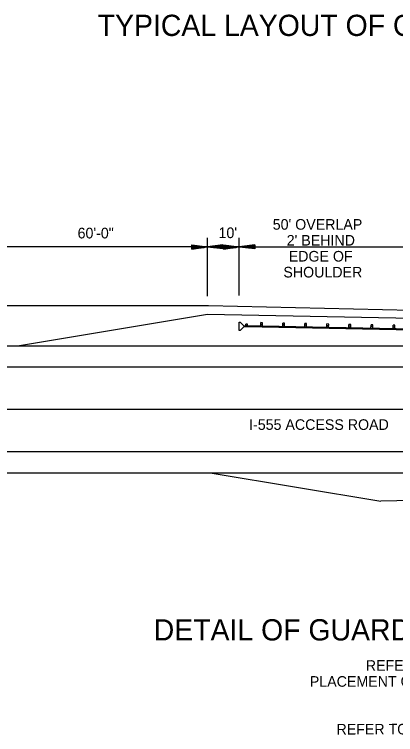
# Model space of a CAD drawing. Extents: x -2842 to 2681, y -2139 to 474.
# Drawn here: x -2490.2 to -2274.9, y -1820.5 to -1413.5 of the extents above; entities that cross this region are included whole.
import ezdxf

# ---------------------------------------------------------------- set-up
doc = ezdxf.new("R2010")
doc.units = 0
for name, color, linetype in [('Default', 7, 'Continuous'), ('R_Border', 7, 'Continuous'), ('R_Border Notes', 7, 'Continuous'), ('R_Grid', 7, 'Continuous')]:
    doc.layers.add(name, color=color, linetype=linetype)

msp = doc.modelspace()

# ---------------------------------------------------------------- linework, layer by layer
at = {"layer": 'Default'}
for p, q in [((-2381.26, -1583.13), (-2488.43, -1600.97)), ((-2263.31, -1585.48), (-2381.26, -1583.13)), ((-2263.45, -1592), (-2359.64, -1590.08)), ((-2359.58, -1589.54), (-2359.56, -1588.54)), ((-2263.43, -1591.46), (-2359.58, -1589.54)), ((-2359.08, -1589.54), (-2359.58, -1589.54)), ((-2358.57, -1588.56), (-2359.56, -1588.54)), ((-2358.59, -1589.56), (-2358.57, -1588.56)), ((-2351.11, -1589.71), (-2351.07, -1587.72)), ((-2350.61, -1589.73), (-2351.11, -1589.71)), ((-2350.09, -1588.73), (-2351.09, -1588.71)), ((-2350.07, -1587.74), (-2351.07, -1587.72)), ((-2350.11, -1589.73), (-2350.61, -1589.73)), ((-2350.11, -1589.73), (-2350.07, -1587.74)), ((-2338.65, -1589.97), (-2338.61, -1587.97)), ((-2338.15, -1589.97), (-2338.65, -1589.97)), ((-2337.63, -1588.99), (-2338.63, -1588.97)), ((-2337.61, -1587.99), (-2338.61, -1587.97)), ((-2337.65, -1589.99), (-2338.15, -1589.97)), ((-2337.65, -1589.99), (-2337.61, -1587.99)), ((-2326.19, -1590.21), (-2326.15, -1588.21)), ((-2325.2, -1589.23), (-2326.19, -1589.21)), ((-2325.71, -1590.23), (-2326.19, -1590.21)), ((-2325.16, -1588.23), (-2326.15, -1588.21)), ((-2325.2, -1590.23), (-2325.71, -1590.23)), ((-2325.2, -1590.23), (-2325.16, -1588.23)), ((-2313.76, -1590.45), (-2313.72, -1588.45)), ((-2313.26, -1590.47), (-2313.76, -1590.45)), ((-2312.74, -1589.49), (-2313.74, -1589.45)), ((-2312.72, -1588.49), (-2313.72, -1588.45)), ((-2312.76, -1590.49), (-2313.26, -1590.47)), ((-2312.76, -1590.49), (-2312.72, -1588.49)), ((-2301.3, -1590.7), (-2301.26, -1588.71)), ((-2300.8, -1590.72), (-2301.3, -1590.7)), ((-2300.28, -1589.73), (-2301.28, -1589.71)), ((-2300.26, -1588.73), (-2301.26, -1588.71)), ((-2300.3, -1590.72), (-2300.8, -1590.72)), ((-2300.3, -1590.72), (-2300.26, -1588.73)), ((-2288.84, -1590.94), (-2288.8, -1588.95)), ((-2288.34, -1590.96), (-2288.84, -1590.94)), ((-2287.83, -1589.97), (-2288.82, -1589.95)), ((-2287.81, -1588.97), (-2288.8, -1588.95)), ((-2287.85, -1590.96), (-2288.34, -1590.96)), ((-2287.85, -1590.96), (-2287.81, -1588.97)), ((-2276.39, -1591.2), (-2276.35, -1589.21)), ((-2275.89, -1591.2), (-2276.39, -1591.2)), ((-2275.37, -1590.23), (-2276.37, -1590.21)), ((-2275.35, -1589.23), (-2276.35, -1589.21)), ((-2275.39, -1591.22), (-2275.89, -1591.2)), ((-2275.39, -1591.22), (-2275.35, -1589.23)), ((-2381.26, -1600.97), (-2773.74, -1600.97)), ((-1815.02, -1600.97), (-2381.26, -1600.97)), ((-1662.85, -1612.93), (-2773.74, -1612.93)), ((-1661.2, -1660.76), (-2773.74, -1660.76)), ((-1815.02, -1672.72), (-2773.74, -1672.72)), ((-2378.47, -1672.72), (-2283.36, -1688.59)), ((-2163.68, -1686.21), (-2283.36, -1688.59))]:
    msp.add_line(p, q, dxfattribs=at)
msp.add_lwpolyline([(-2500.66, -1577.94), (-2380.62, -1578.11), (-2266.04, -1580.67)], dxfattribs=at)
msp.add_lwpolyline([(-2360.71, -1589.52), (-2359.22, -1589.54), (-2359.24, -1590.08), (-2360.73, -1590.06), (-2362.69, -1592.09), (-2363.34, -1592.07), (-2363.32, -1587.47), (-2362.67, -1587.49)], close=True, dxfattribs=at)
at = {"layer": 'R_Border Notes'}
for p, q in [((-2381.26, -1572.68), (-2381.26, -1539.7)), ((-2363.24, -1572.28), (-2363.24, -1539.7)), ((-2363.24, -1544.95), (-2500.85, -1544.95)), ((-2390.09, -1543.81), (-2381.26, -1544.95)), ((-2390.08, -1546.1), (-2390.09, -1543.81)), ((-2390.09, -1544.03), (-2388.36, -1544.03)), ((-2390.09, -1544.27), (-2386.57, -1544.26)), ((-2390.09, -1544.49), (-2384.78, -1544.5)), ((-2390.09, -1544.73), (-2383.05, -1544.73)), ((-2381.26, -1544.95), (-2390.09, -1544.95)), ((-2390.09, -1545.41), (-2384.78, -1545.4)), ((-2390.09, -1545.87), (-2388.35, -1545.86)), ((-2390.08, -1546.1), (-2381.26, -1544.95)), ((-2390.08, -1545.18), (-2383.05, -1545.18)), ((-2390.08, -1545.64), (-2386.56, -1545.64)), ((-2372.44, -1543.8), (-2381.26, -1544.95)), ((-2381.26, -1544.95), (-2372.44, -1544.95)), ((-2372.44, -1546.09), (-2381.26, -1544.95)), ((-2372.44, -1544.72), (-2379.47, -1544.72)), ((-2372.44, -1545.17), (-2379.47, -1545.18)), ((-2372.44, -1544.49), (-2377.74, -1544.5)), ((-2372.43, -1545.41), (-2377.74, -1545.41)), ((-2372.44, -1544.26), (-2375.96, -1544.26)), ((-2372.43, -1545.63), (-2375.96, -1545.64)), ((-2372.44, -1544.03), (-2374.17, -1544.04)), ((-2372.44, -1545.87), (-2374.17, -1545.87)), ((-2372.44, -1543.8), (-2372.44, -1546.09)), ((-2372.07, -1543.81), (-2363.24, -1544.95)), ((-2372.07, -1546.1), (-2372.07, -1543.81)), ((-2372.07, -1544.03), (-2370.34, -1544.03)), ((-2372.07, -1544.27), (-2368.55, -1544.26)), ((-2372.07, -1544.49), (-2366.77, -1544.5)), ((-2372.07, -1544.73), (-2365.04, -1544.73)), ((-2363.24, -1544.95), (-2372.07, -1544.95)), ((-2372.07, -1546.1), (-2363.24, -1544.95)), ((-2372.07, -1545.41), (-2366.76, -1545.4)), ((-2372.07, -1545.87), (-2370.33, -1545.86)), ((-2372.06, -1545.18), (-2365.03, -1545.18)), ((-2372.06, -1545.64), (-2368.55, -1545.64)), ((-2354.42, -1543.8), (-2363.24, -1544.95)), ((-2363.24, -1544.95), (-1716.57, -1544.95)), ((-2363.24, -1544.95), (-2354.42, -1544.95)), ((-2354.42, -1546.09), (-2363.24, -1544.95)), ((-2354.42, -1544.72), (-2361.45, -1544.72)), ((-2354.42, -1545.17), (-2361.45, -1545.18)), ((-2354.42, -1544.49), (-2359.72, -1544.5)), ((-2354.41, -1545.41), (-2359.72, -1545.41)), ((-2354.43, -1544.26), (-2357.94, -1544.26)), ((-2354.42, -1545.63), (-2357.94, -1545.64)), ((-2354.42, -1544.03), (-2356.16, -1544.04)), ((-2354.42, -1545.87), (-2356.15, -1545.87)), ((-2354.42, -1543.8), (-2354.42, -1546.09))]:
    msp.add_line(p, q, dxfattribs=at)
at = {"layer": 'R_Grid'}
msp.add_line((-1662.85, -1636.84), (-2773.74, -1636.84), dxfattribs=at)

# ---------------------------------------------------------------- texts
at = {"layer": 'R_Border'}
for s, height, rotation, p in [('TYPICAL LAYOUT OF GUARDRAIL AT BRIDGE ENDS', 12, 359.9999, (-2443.18, -1425.69)), ('I-555 ACCESS ROAD', 6, 359.9999, (-2357.67, -1648.33)), ('DETAIL OF GUARD CABLE AT BRIDGE ENDS', 12, 359.9999, (-2411.53, -1767.33)), ('REFER TO PLANS FOR RELATIVE ', 6, 0.0775, (-2291.78, -1784.47)), ('PLACEMENT OF GUARDRAIL AND GUARD CABLE', 6, 0.0775, (-2323.37, -1793.51)), ('REFER TO STANDARD DRAWING GC-1 FOR ', 6, 0.0775, (-2308.33, -1820.49))]:
    msp.add_text(s, height=height, rotation=rotation, dxfattribs=at).set_placement(p)
for s, p in [("50' OVERLAP", (-2344.32, -1535.19)), ('60\'-0"', (-2454.53, -1540.11)), ("10'", (-2374.94, -1539.92)), ("2' BEHIND ", (-2336.43, -1544.19)), ('EDGE OF ', (-2335.29, -1553.19)), ('SHOULDER', (-2338.32, -1562.19))]:
    msp.add_text(s, height=6, dxfattribs=at).set_placement(p)

doc.saveas('drawing.dxf')
